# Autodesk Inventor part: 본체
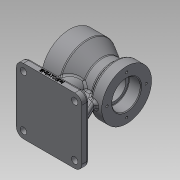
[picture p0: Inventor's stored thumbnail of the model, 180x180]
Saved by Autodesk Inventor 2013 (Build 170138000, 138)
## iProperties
Created: 2019-01
Part Number: 본체
Material: 일반
Document SubType Name: Modeling
Designer: hana-cad16
Density: 1 g/cm^3
Author: hana-cad16
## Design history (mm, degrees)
sketch "스케치1"
  geometry: L1 (0, 0)-(80, 0); L2 (0, 26)-(0, 40); L3 (0, 40)-(25, 40); L4 (80, 20)-(80, 35); L5 (80, 35)-(65, 35); L6 (25, 40)-(43.113, 29.543); L7 (45.785, 28)-(59.126, 28); L8 (43.113, 29.543)-(45.785, 28); L9 (65, 35)-(59.126, 28); L10 (0, 26)-(20, 26); L11 (20, 26)-(20, 16); L12 (80, 20)-(63, 20); L13 (20, 16)-(63, 16); L14 (63, 16)-(63, 20)
  constraints: 28 end point, 5 perpendicular, 1 collinear, 1 horizontal, 1 parallel
  dimensions: "d2" = 25 distance of L2.end L3.end; "d3" = 70 diameter of L4.end L1; "d10" = 32 diameter of L11.end L1
revolve "회전1" sketch "스케치1" stored, may be unused: angle "d13" = 90 deg
chamfer "모따기1" distance "d14" = 1; stored, may be unused: second distance "d15" = 2, angle "d16" = 45 deg
fillet "모깎기1" dims "d17" = 1
fillet "모깎기2" dims "d18" = 0.6
sketch "스케치3" dims "d19" = 55
  geometry: C1 r 21 at (0, 0) reference; C2 r 3.873 at (0, 27.5); 1 further point
  constraints: 1 centre point, 1 coincident, 1 vertical alignment, 2 other
hole "구멍1" sketch "스케치3" at (0, 27.5) diameter "d20" = 3.242; stored, may be unused: countersink angle "d24" = 90 deg, drill point angle "d26" = 118 deg; dims "d21" = 9, "d22" = 4, "d23" = 2, "d25" = 11
sketch "스케치4" dims "d30" = 66
  geometry: C1 r 27 at (0, 0) reference; C2 r 3.501 at (0, 33); 1 further point
  constraints: 1 centre point, 1 coincident, 1 vertical alignment, 2 other
hole "구멍2" sketch "스케치4" at (0, 33) diameter "d31" = 3.242; stored, may be unused: countersink angle "d35" = 90 deg, drill point angle "d37" = 118 deg; dims "d32" = 9, "d33" = 4, "d34" = 2, "d36" = 11
node "작업 평면1"
sketch "스케치5"
  geometry: L1 (0, 40)-(0, -40) reference; L2 (0, 0)-(-5, 0); L3 (-5, 0)-(-5, -46); L4 (-5, 0)-(-5, 46); L5 (-5, -46)-(-97, -46); L6 (-97, -46)-(-97, 46); L7 (-97, 46)-(-5, 46); L8 (-5, 46)-(-5, -46)
  constraints: 14 end point, 3 equal length, 3 perpendicular, 1 horizontal
  dimensions: "d45" = 92 distance of L6.end L7.end
extrude "돌출1" join sketch "스케치5" distance "d46" = 10; taper "d47" = 0 deg
fillet "모깎기3" dims "d48" = 10
sketch "스케치6"
  geometry: C1 r 4.5 at (15, 36); C2 r 4.5 at (87, 36); C3 r 4.5 at (15, -36); C4 r 4.5 at (87, -36); A1 r 10 centre (15, -36) between (5, -36) and (15, -46) reference; A2 r 10 centre (87, -36) between (87, -46) and (97, -36) reference; A3 r 10 centre (87, 36) between (97, 36) and (87, 46) reference; A4 r 10 centre (15, 36) between (15, 46) and (5, 36) reference; 1 further point
  constraints: 4 centre point, 4 coincident
  dimensions: "d49" = 9 diameter of C1; "d50" = 9 diameter of C2; "d51" = 9 diameter of C3; "d52" = 9 diameter of C4
extrude "돌출2" cut sketch "스케치6" stored distance "d53" = 10; taper "d54" = 0 deg
sketch "스케치7"
  geometry: L1 (97, -36)-(97, 36) reference; L2 (5, 36)-(5, -36) reference; L3 (87, 46)-(15, 46) reference; L4 (5, 0)-(5, 46); L5 (5, 46)-(35, 46); L6 (5, 0)-(97, 0); C1 r 16 at (35, 0); 1 further point
  constraints: 6 end point, 2 midpoint, 2 point on line, 1 centre point
  dimensions: "d55" = 46 distance of L4.start L4.end; "d56" = 30 distance of L4.end L5.end; "d57" = 32 diameter of C1
fillet "모깎기4" dims "d58" = 3
extrude "돌출3" join sketch "스케치7" stored distance "d59" = 10; taper "d60" = 0 deg
sketch "스케치8"
  geometry: L1 (97, -70)-(97, -80) reference; L2 (97, -70)-(87, -70); L3 (87, -70)-(68.58, -30.499); L4 (68.58, -30.499)-(56.144, -25.185); L5 (56.144, -25.185)-(45.332, -25.185); L6 (45.332, -25.185)-(45.332, -73.432); L7 (45.332, -73.432)-(78.814, -75); L8 (78.814, -75)-(92, -70); 1 further point
  constraints: 14 end point, 2 perpendicular, 1 midpoint, 1 parallel
  dimensions: "d61" = 10 distance of L1.start L2.end; "d62" = 25 deg angle of L1 L3
extrude "돌출4" join sketch "스케치8" stored distance "d63" = 10; taper "d64" = 0 deg
fillet "모깎기5" dims "d65" = 3
fillet "모깎기6" dims "d66" = 3
fillet "모깎기7" dims "d67" = 3
node "작업 평면2"
sketch "스케치9"
  geometry: L1 (5, -73)-(5, -80) reference; L2 (15, -80)-(87, -80) reference; 2 further points
  constraints: 1 other
  dimensions: "d69" = 46 distance from line of point (51, -76) L1; "d70" = 4 distance from line of L2 point (51, -76)
feature "엠보싱1" sketch "스케치9" dims "d71" = 0.5, "d72" = 0
node "솔리드1"
pattern_circular "원형 패턴1" dims angle "d28" = 360 deg
pattern_circular "원형 패턴2" dims angle "d39" = 360 deg
other parameters: "d68" = 51.25
